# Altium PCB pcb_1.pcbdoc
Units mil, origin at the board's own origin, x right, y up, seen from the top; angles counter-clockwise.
Board outline 3399.99 x 1728.27 mil, 2 copper layers (Top Layer, Bottom Layer); 16 components, 0 nets, 64 pads, 0 vias.
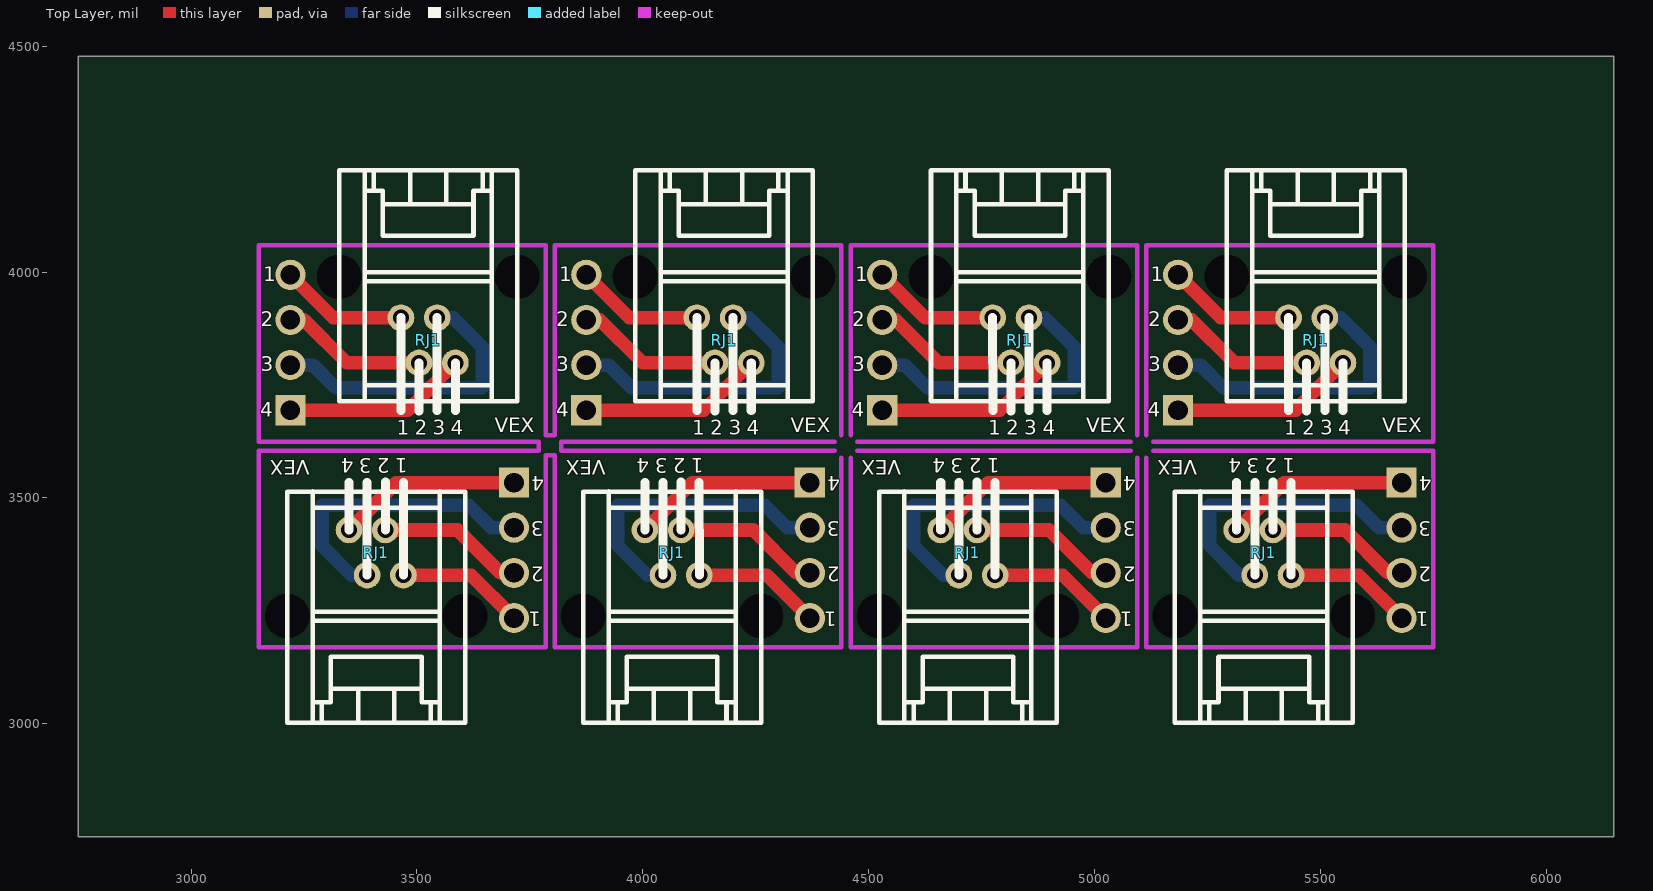
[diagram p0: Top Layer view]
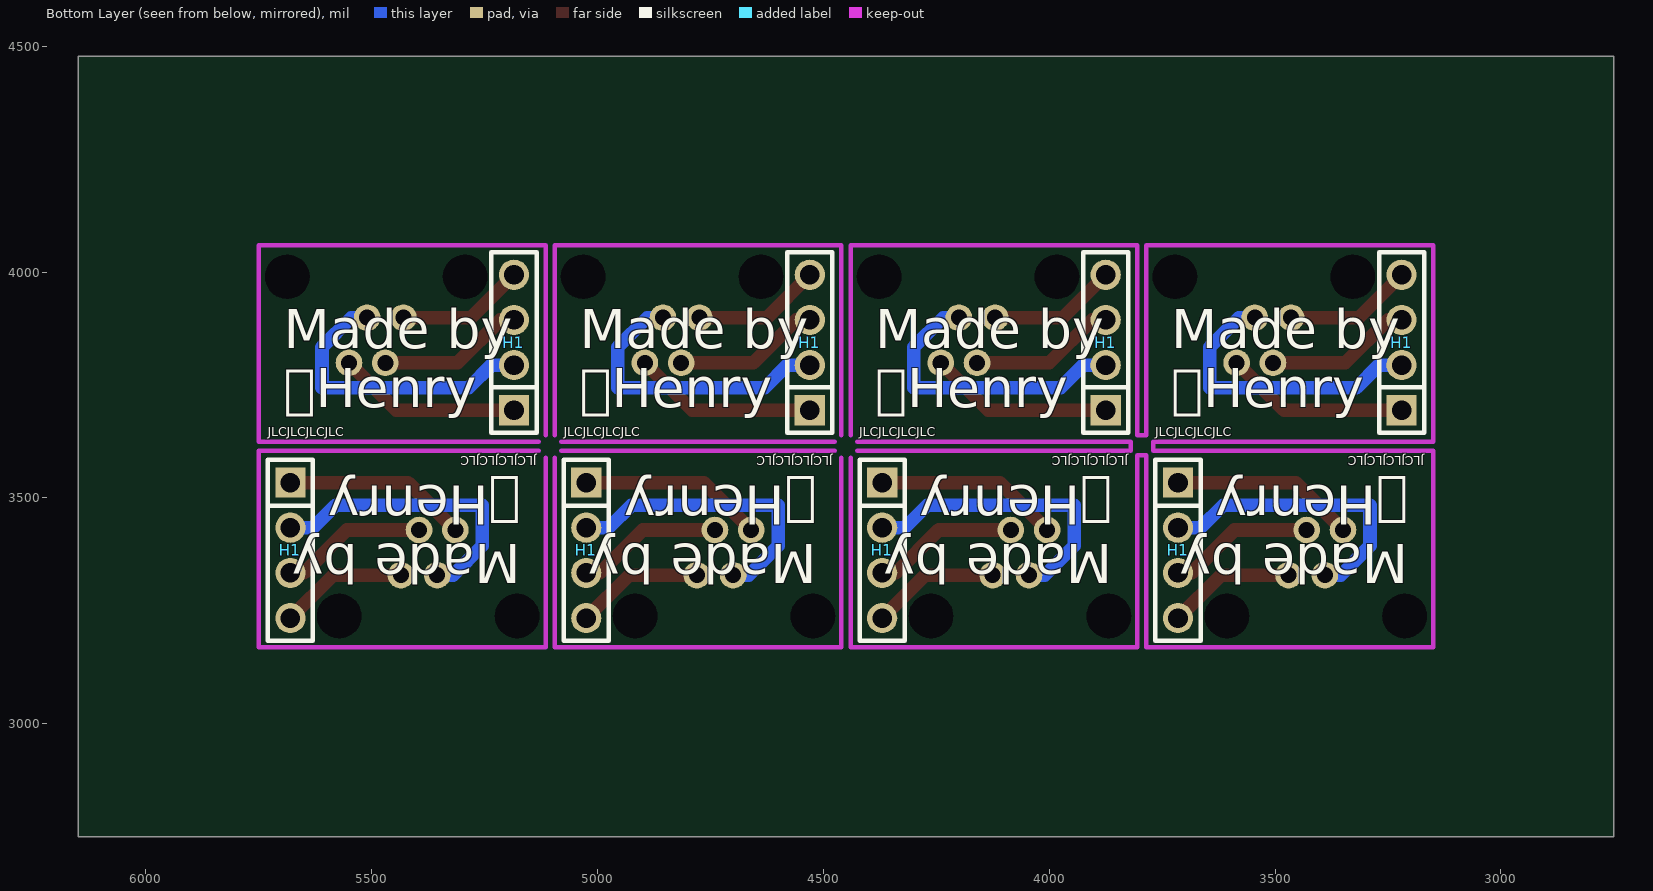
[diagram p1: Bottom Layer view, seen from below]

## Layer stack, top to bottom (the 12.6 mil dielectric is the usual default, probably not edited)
Top Layer: signal copper (thickness not stored)
Dielectric: dielectric 12.6, FR-4, Dk 4.8
Bottom Layer: signal copper (thickness not stored)

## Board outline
6149.99,2750 2750,2750 2750,4478.27 6149.99,4478.27

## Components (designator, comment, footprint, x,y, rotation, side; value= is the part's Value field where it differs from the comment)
H1 "KH-2.54PH180-1X4P-L11.5" HDR-TH_4P-P2.54-V-M 3220,3844.13 r90 bottom
H1 "KH-2.54PH180-1X4P-L11.5" HDR-TH_4P-P2.54-V-M 3875.01,3844.13 r90 bottom
H1 "KH-2.54PH180-1X4P-L11.5" HDR-TH_4P-P2.54-V-M 3714.99,3384.13 r270 bottom
H1 "KH-2.54PH180-1X4P-L11.5" HDR-TH_4P-P2.54-V-M 4369.99,3384.13 r270 bottom
H1 "KH-2.54PH180-1X4P-L11.5" HDR-TH_4P-P2.54-V-M 4530.01,3844.13 r90 bottom
H1 "KH-2.54PH180-1X4P-L11.5" HDR-TH_4P-P2.54-V-M 5185.01,3844.13 r90 bottom
H1 "KH-2.54PH180-1X4P-L11.5" HDR-TH_4P-P2.54-V-M 5024.99,3384.13 r270 bottom
H1 "KH-2.54PH180-1X4P-L11.5" HDR-TH_4P-P2.54-V-M 5679.99,3384.13 r270 bottom
RJ1 "R-RJ11R04P-A802" RJ11-TH_616-PCB-4P4C-90 3525,3849.13 r90 top
RJ1 "R-RJ11R04P-A802" RJ11-TH_616-PCB-4P4C-90 4180.01,3849.13 r90 top
RJ1 "R-RJ11R04P-A802" RJ11-TH_616-PCB-4P4C-90 3409.99,3379.13 r270 top
RJ1 "R-RJ11R04P-A802" RJ11-TH_616-PCB-4P4C-90 4064.99,3379.13 r270 top
RJ1 "R-RJ11R04P-A802" RJ11-TH_616-PCB-4P4C-90 4835.01,3849.13 r90 top
RJ1 "R-RJ11R04P-A802" RJ11-TH_616-PCB-4P4C-90 5490.01,3849.13 r90 top
RJ1 "R-RJ11R04P-A802" RJ11-TH_616-PCB-4P4C-90 4719.99,3379.13 r270 top
RJ1 "R-RJ11R04P-A802" RJ11-TH_616-PCB-4P4C-90 5374.99,3379.13 r270 top

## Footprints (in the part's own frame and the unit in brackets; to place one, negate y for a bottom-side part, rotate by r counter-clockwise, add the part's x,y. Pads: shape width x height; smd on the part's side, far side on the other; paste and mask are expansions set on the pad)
HDR-TH_4P-P2.54-V-M [mm]
  rect 1.7x1.7 hole 1.1: 1(-3.81,0)
  round 1.7 hole 1.1: 2(-1.27,0) 3(1.27,0) 4(3.81,0)
  silkscreen extent -5.08,-1.27 5.08,1.27
RJ11-TH_616-PCB-4P4C-90 [mm]
  round 1.5 hole 0.9: 1(1.27,1.53) 2(-1.27,0.51) 3(1.27,-0.51) 4(-1.27,-1.53)
  Multi-Layer board cut-out: 3.57,3.75 4.112,3.874 4.547,4.221 4.789,4.722 4.789,5.278 4.547,5.779 4.112,6.126 3.57,6.25 3.57,6.25 3.028,6.126 2.593,5.779 2.351,5.278 2.351,4.722 2.593,4.221 3.028,3.874 3.57,3.75
  Multi-Layer board cut-out: 3.57,-6.25 4.112,-6.126 4.547,-5.779 4.789,-5.278 4.789,-4.722 4.547,-4.22 4.112,-3.874 3.57,-3.75 3.57,-3.75 3.028,-3.874 2.593,-4.22 2.351,-4.722 2.351,-5.278 2.593,-5.779 3.028,-6.126 3.57,-6.25
  silkscreen extent -3.44,-5 9.57,5

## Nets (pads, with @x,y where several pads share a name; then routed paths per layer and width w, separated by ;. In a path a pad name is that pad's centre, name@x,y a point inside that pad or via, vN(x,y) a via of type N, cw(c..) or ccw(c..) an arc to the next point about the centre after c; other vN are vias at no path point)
pads on no net: H1.1 H1.2 H1.3 H1.4 RJ1.1 RJ1.2 RJ1.3 RJ1.4
copper on no net: | length 13437.3
  Top Layer w30: 3220,3694.13 3480.24,3694.13 3585.24,3799.13 ; 3220,3894.13 3250,3894.13 3345,3799.13 3504.91,3799.13 ; 3220,3994.13 3315,3899.13 3464.76,3899.13 ; 3349.76,3429.13 3454.76,3534.13 3714.99,3534.13 ; 3430.08,3429.13 3589.99,3429.13 3684.99,3334.13 3714.99,3334.13 ; 3470.23,3329.13 3619.99,3329.13 3714.99,3234.13 ; 3875.01,3694.13 4135.24,3694.13 4240.24,3799.13 ; 3875.01,3894.13 3905.01,3894.13 4000.01,3799.13 4159.92,3799.13 ; 3875.01,3994.13 3970.01,3899.13 4119.77,3899.13 ; 4004.76,3429.13 4109.76,3534.13 4369.99,3534.13 ; 4085.08,3429.13 4244.99,3429.13 4339.99,3334.13 4369.99,3334.13 ; 4125.23,3329.13 4274.99,3329.13 4369.99,3234.13 ; 4530.01,3694.13 4790.24,3694.13 4895.24,3799.13 ; 4530.01,3894.13 4560.01,3894.13 4655.01,3799.13 4814.92,3799.13 ; 4530.01,3994.13 4625.01,3899.13 4774.77,3899.13 ; 4659.76,3429.13 4764.76,3534.13 5024.99,3534.13 ; 4740.08,3429.13 4899.99,3429.13 4994.99,3334.13 5024.99,3334.13 ; 4780.23,3329.13 4929.99,3329.13 5024.99,3234.13 ; 5185.01,3694.13 5445.24,3694.13 5550.24,3799.13 ; 5185.01,3894.13 5215.01,3894.13 5310.01,3799.13 5469.92,3799.13 ; 5185.01,3994.13 5280.01,3899.13 5429.77,3899.13 ; 5314.76,3429.13 5419.76,3534.13 5679.99,3534.13 ; 5395.08,3429.13 5554.99,3429.13 5649.99,3334.13 5679.99,3334.13 ; 5435.23,3329.13 5584.99,3329.13 5679.99,3234.13
  Bottom Layer w30: 3220,3794.13 3270,3794.13 3320,3744.13 3645,3744.13 3645,3834.13 3580,3899.13 3545.07,3899.13 ; 3389.92,3329.13 3354.99,3329.13 3289.99,3394.13 3289.99,3484.13 3614.99,3484.13 3664.99,3434.13 3714.99,3434.13 ; 3875.01,3794.13 3925.01,3794.13 3975.01,3744.13 4300.01,3744.13 4300.01,3834.13 4235.01,3899.13 4200.08,3899.13 ; 4044.92,3329.13 4009.99,3329.13 3944.99,3394.13 3944.99,3484.13 4269.99,3484.13 4319.99,3434.13 4369.99,3434.13 ; 4530.01,3794.13 4580.01,3794.13 4630.01,3744.13 4955.01,3744.13 4955.01,3834.13 4890.01,3899.13 4855.08,3899.13 ; 4699.92,3329.13 4664.99,3329.13 4599.99,3394.13 4599.99,3484.13 4924.99,3484.13 4974.99,3434.13 5024.99,3434.13 ; 5185.01,3794.13 5235.01,3794.13 5285.01,3744.13 5610.01,3744.13 5610.01,3834.13 5545.01,3899.13 5510.08,3899.13 ; 5354.92,3329.13 5319.99,3329.13 5254.99,3394.13 5254.99,3484.13 5579.99,3484.13 5629.99,3434.13 5679.99,3434.13

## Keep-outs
Board Outline Layer:
  lines w10: 4425,3604.13 3820,3604.13 3820,3624.13 4425,3624.13 ; 4440,3589.13 4440,3169.13 3805,3169.13 3805,3594.13 3785,3594.13 3785,3169.13 3150,3169.13 3150,3604.13 3770,3604.13 3770,3624.13 3149.99,3624.13 3149.99,4059.13 3784.99,4059.13 3785,3639.13 3805,3639.13 3805,4059.13 4440,4059.13 4440,3639.13 ; 4460,3589.13 4460,3169.13 5095,3169.13 5095,3589.13 ; 4460,3639.13 4460,4059.13 5095,4059.13 5095,3639.13 ; 4475,3604.13 5080,3604.13 ; 4475,3624.13 5080,3624.13 ; 5115,3589.13 5115,3169.13 5750,3169.13 5750,3604.13 5130,3604.13 ; 5115,3639.13 5115,4059.13 5750,4059.13 5750,3624.13 5130,3624.13

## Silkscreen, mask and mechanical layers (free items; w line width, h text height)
Top Silkscreen Layer:
  lines w20: 3349.76,3429.13 3349.76,3534.57 ; 3389.92,3329.13 3389.92,3534.57 ; 3430.08,3429.13 3430.08,3535.55 ; 3464.76,3899.13 3465,3694.13 ; 3469.99,3534.13 3470.23,3329.13 ; 3504.91,3692.72 3504.91,3799.13 ; 3545.07,3693.7 3545.07,3899.13 ; 3585.24,3693.7 3585.24,3799.13 ; 4004.76,3429.13 4004.76,3534.57 ; 4044.92,3329.13 4044.92,3534.57 ; 4085.08,3429.13 4085.08,3535.55 ; 4119.77,3899.13 4120.01,3694.13 ; 4124.99,3534.13 4125.23,3329.13 ; 4159.92,3692.72 4159.92,3799.13 ; 4200.08,3693.7 4200.08,3899.13 ; 4240.24,3693.7 4240.24,3799.13 ; 4659.76,3429.13 4659.76,3534.57 ; 4699.92,3329.13 4699.92,3534.57 ; 4740.08,3429.13 4740.08,3535.55 ; 4774.77,3899.13 4775.01,3694.13 ; 4779.99,3534.13 4780.23,3329.13 ; 4814.92,3692.72 4814.92,3799.13 ; 4855.08,3693.7 4855.08,3899.13 ; 4895.24,3693.7 4895.24,3799.13 ; 5314.76,3429.13 5314.76,3534.57 ; 5354.92,3329.13 5354.92,3534.57 ; 5395.08,3429.13 5395.08,3535.55 ; 5429.77,3899.13 5430.01,3694.13 ; 5434.99,3534.13 5435.23,3329.13 ; 5469.92,3692.72 5469.92,3799.13 ; 5510.08,3693.7 5510.08,3899.13 ; 5550.24,3693.7 5550.24,3799.13
  text "1" at 3160,3980.12 h32.69
  text "1" at 3815.01,3980.12 h32.69
  text "1" at 4470.01,3980.12 h32.69
  text "1" at 5125.01,3980.12 h32.69
  text "2" at 3153.95,3880.12 h32.69
  text "2" at 3808.95,3880.12 h32.69
  text "2" at 4463.95,3880.12 h32.69
  text "2" at 5118.95,3880.12 h32.69
  text "3" at 3153.95,3780.12 h32.69
  text "3" at 3808.95,3780.12 h32.69
  text "3" at 4463.95,3780.12 h32.69
  text "3" at 5118.95,3780.12 h32.69
  text "4" at 3153.25,3680.12 h32.69
  text "4" at 3808.26,3680.12 h32.69
  text "4" at 4463.26,3680.12 h32.69
  text "4" at 5118.26,3680.12 h32.69
  text "VEX" at 3672.23,3645.23 h32.45
  text "VEX" at 4327.23,3645.23 h32.45
  text "VEX" at 4982.23,3645.23 h32.45
  text "VEX" at 5637.23,3645.23 h32.45
  text "1" at 3455,3640.12 h32.69
  text "2" at 3495,3640.12 h32.69
  text "3" at 3535,3640.12 h32.69
  text "4" at 3575,3640.12 h32.69
  text "1" at 4110.01,3640.12 h32.69
  text "2" at 4150.01,3640.12 h32.69
  text "3" at 4190.01,3640.12 h32.69
  text "4" at 4230.01,3640.12 h32.69
  text "1" at 4765.01,3640.12 h32.69
  text "2" at 4805.01,3640.12 h32.69
  text "3" at 4845.01,3640.12 h32.69
  text "4" at 4885.01,3640.12 h32.69
  text "1" at 5420.01,3640.12 h32.69
  text "2" at 5460.01,3640.12 h32.69
  text "3" at 5500.01,3640.12 h32.69
  text "4" at 5540.01,3640.12 h32.69
  text "4" at 3359.99,3588.15 h32.69 r180
  text "3" at 3399.99,3588.15 h32.69 r180
  text "2" at 3439.99,3588.15 h32.69 r180
  text "1" at 3479.99,3588.15 h32.69 r180
  text "4" at 4014.99,3588.15 h32.69 r180
  text "3" at 4054.99,3588.15 h32.69 r180
  text "2" at 4094.99,3588.15 h32.69 r180
  text "1" at 4134.99,3588.15 h32.69 r180
  text "4" at 4669.99,3588.15 h32.69 r180
  text "3" at 4709.99,3588.15 h32.69 r180
  text "2" at 4749.99,3588.15 h32.69 r180
  text "1" at 4789.99,3588.15 h32.69 r180
  text "4" at 5324.99,3588.15 h32.69 r180
  text "3" at 5364.99,3588.15 h32.69 r180
  text "2" at 5404.99,3588.15 h32.69 r180
  text "1" at 5444.99,3588.15 h32.69 r180
  text "VEX" at 3262.77,3583.03 h32.45 r180
  text "VEX" at 3917.77,3583.03 h32.45 r180
  text "VEX" at 4572.77,3583.03 h32.45 r180
  text "VEX" at 5227.77,3583.03 h32.45 r180
  text "4" at 3781.74,3548.15 h32.69 r180
  text "4" at 4436.74,3548.15 h32.69 r180
  text "4" at 5091.74,3548.15 h32.69 r180
  text "4" at 5746.74,3548.15 h32.69 r180
  text "3" at 3781.05,3448.15 h32.69 r180
  text "3" at 4436.05,3448.15 h32.69 r180
  text "3" at 5091.05,3448.15 h32.69 r180
  text "3" at 5746.05,3448.15 h32.69 r180
  text "2" at 3781.05,3348.15 h32.69 r180
  text "2" at 4436.05,3348.15 h32.69 r180
  text "2" at 5091.05,3348.15 h32.69 r180
  text "2" at 5746.05,3348.15 h32.69 r180
  text "1" at 3774.99,3248.15 h32.69 r180
  text "1" at 4429.99,3248.15 h32.69 r180
  text "1" at 5084.99,3248.15 h32.69 r180
  text "1" at 5739.99,3248.15 h32.69 r180
Bottom Silkscreen Layer:
  text "Made by /  Henry" at 3729.84,3700.77 h86.82
  text "Made by /  Henry" at 4384.85,3700.77 h86.82
  text "Made by /  Henry" at 5039.85,3700.77 h86.82
  text "Made by /  Henry" at 5694.85,3700.77 h86.82
  text "JLCJLCJLCJLC" at 3765.18,3636.13 h20.44
  text "JLCJLCJLCJLC" at 4420.18,3636.13 h20.44
  text "JLCJLCJLCJLC" at 5075.18,3636.13 h20.44
  text "JLCJLCJLCJLC" at 5730.18,3636.13 h20.44
  text "JLCJLCJLCJLC" at 3169.82,3592.14 h20.44 r180
  text "JLCJLCJLCJLC" at 3824.82,3592.14 h20.44 r180
  text "JLCJLCJLCJLC" at 4479.82,3592.14 h20.44 r180
  text "JLCJLCJLCJLC" at 5134.82,3592.14 h20.44 r180
  text "Made by /  Henry" at 3205.15,3527.49 h86.82 r180
  text "Made by /  Henry" at 3860.15,3527.49 h86.82 r180
  text "Made by /  Henry" at 4515.15,3527.49 h86.82 r180
  text "Made by /  Henry" at 5170.15,3527.49 h86.82 r180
